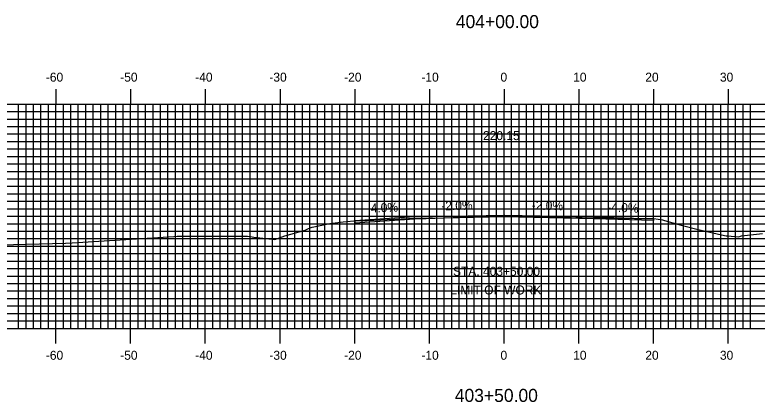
# Model space of a CAD drawing. Extents: x 850955 to 851298, y 364785 to 365005.
# Drawn here: x 851055.2 to 851154.6, y 364893.4 to 364945.2 of the extents above; entities that cross this region are included whole.
import ezdxf

# ---------------------------------------------------------------- set-up
doc = ezdxf.new("R2010")
doc.units = 0
for name, color, linetype in [('ANNOTATION', 7, 'Continuous'), ('D_Roadway_Centerline', 7, 'Continuous'), ('D_Roadway_Centerline_Text', 7, 'Continuous'), ('D_Roadway_Edge_Shoulder', 7, 'Continuous'), ('D_Roadway_Edge_TW', 7, 'Continuous'), ('D_Text_Standard', 7, 'Continuous'), ('H_V ANNOTATION', 7, 'Continuous'), ('MAJOR', 7, 'Continuous'), ('MINOR', 7, 'Continuous'), ('S_Roadway_Centerline', 7, 'Continuous')]:
    doc.layers.add(name, color=color, linetype=linetype)

msp = doc.modelspace()

# ---------------------------------------------------------------- linework, layer by layer
at = {"layer": 'D_Roadway_Edge_Shoulder'}
for points in [[(851108.678, 364918.143), (851100.678, 364917.609), (851100.678, 364917.359), (851108.678, 364917.893)], [(851132.678, 364918.143), (851140.678, 364917.904), (851140.678, 364917.654), (851132.678, 364917.893)]]:
    msp.add_lwpolyline(points, close=True, dxfattribs=at)
at = {"layer": 'D_Roadway_Edge_TW'}
msp.add_lwpolyline([(851108.678, 364917.893), (851108.678, 364918.143), (851120.678, 364918.383), (851132.678, 364918.143), (851132.678, 364917.893), (851120.678, 364918.133)], close=True, dxfattribs=at)
at = {"layer": 'MAJOR'}
for p, q in [((851060.678, 364935.237), (851060.678, 364933.233)), ((851070.678, 364935.237), (851070.678, 364933.233)), ((851080.678, 364935.237), (851080.678, 364933.233)), ((851090.678, 364935.237), (851090.678, 364933.233)), ((851100.678, 364935.237), (851100.678, 364933.233)), ((851110.678, 364935.237), (851110.678, 364933.233)), ((851120.678, 364935.237), (851120.678, 364933.233)), ((851130.678, 364935.237), (851130.678, 364933.233)), ((851140.678, 364935.237), (851140.678, 364933.233)), ((851150.678, 364935.237), (851150.678, 364933.233)), ((850980.678, 364933.233), (851260.678, 364933.233)), ((850980.678, 364933.233), (851260.678, 364933.233)), ((851060.678, 364903.233), (851060.678, 364933.233)), ((851070.678, 364903.233), (851070.678, 364933.233)), ((851080.678, 364903.233), (851080.678, 364933.233)), ((851090.678, 364903.233), (851090.678, 364933.233)), ((851100.678, 364903.233), (851100.678, 364933.233)), ((851110.678, 364903.233), (851110.678, 364933.233)), ((851120.678, 364903.233), (851120.678, 364933.233)), ((851130.678, 364903.233), (851130.678, 364933.233)), ((851140.678, 364903.233), (851140.678, 364933.233)), ((851150.678, 364903.233), (851150.678, 364933.233)), ((850980.678, 364928.233), (851260.678, 364928.233)), ((850980.678, 364923.233), (851260.678, 364923.233)), ((850980.678, 364918.233), (851260.678, 364918.233)), ((850980.678, 364913.233), (851260.678, 364913.233)), ((850980.678, 364908.233), (851260.678, 364908.233)), ((850980.678, 364903.233), (851260.678, 364903.233)), ((850980.678, 364903.233), (851260.678, 364903.233)), ((851060.678, 364901.229), (851060.678, 364903.233)), ((851070.678, 364901.229), (851070.678, 364903.233)), ((851080.678, 364901.229), (851080.678, 364903.233)), ((851090.678, 364901.229), (851090.678, 364903.233)), ((851100.678, 364901.229), (851100.678, 364903.233)), ((851110.678, 364901.229), (851110.678, 364903.233)), ((851120.678, 364901.229), (851120.678, 364903.233)), ((851130.678, 364901.229), (851130.678, 364903.233)), ((851140.678, 364901.229), (851140.678, 364903.233)), ((851150.678, 364901.229), (851150.678, 364903.233))]:
    msp.add_line(p, q, dxfattribs=at)
at = {"layer": 'MINOR'}
for p, q in [((851055.678, 364903.233), (851055.678, 364933.233)), ((851056.678, 364903.233), (851056.678, 364933.233)), ((851057.678, 364903.233), (851057.678, 364933.233)), ((851058.678, 364903.233), (851058.678, 364933.233)), ((851059.678, 364903.233), (851059.678, 364933.233)), ((851061.678, 364903.233), (851061.678, 364933.233)), ((851062.678, 364903.233), (851062.678, 364933.233)), ((851063.678, 364903.233), (851063.678, 364933.233)), ((851064.678, 364903.233), (851064.678, 364933.233)), ((851065.678, 364903.233), (851065.678, 364933.233)), ((851066.678, 364903.233), (851066.678, 364933.233)), ((851067.678, 364903.233), (851067.678, 364933.233)), ((851068.678, 364903.233), (851068.678, 364933.233)), ((851069.678, 364903.233), (851069.678, 364933.233)), ((851071.678, 364903.233), (851071.678, 364933.233)), ((851072.678, 364903.233), (851072.678, 364933.233)), ((851073.678, 364903.233), (851073.678, 364933.233)), ((851074.678, 364903.233), (851074.678, 364933.233)), ((851075.678, 364903.233), (851075.678, 364933.233)), ((851076.678, 364903.233), (851076.678, 364933.233)), ((851077.678, 364903.233), (851077.678, 364933.233)), ((851078.678, 364903.233), (851078.678, 364933.233)), ((851079.678, 364903.233), (851079.678, 364933.233)), ((851081.678, 364903.233), (851081.678, 364933.233)), ((851082.678, 364903.233), (851082.678, 364933.233)), ((851083.678, 364903.233), (851083.678, 364933.233)), ((851084.678, 364903.233), (851084.678, 364933.233)), ((851085.678, 364903.233), (851085.678, 364933.233)), ((851086.678, 364903.233), (851086.678, 364933.233)), ((851087.678, 364903.233), (851087.678, 364933.233)), ((851088.678, 364903.233), (851088.678, 364933.233)), ((851089.678, 364903.233), (851089.678, 364933.233)), ((851091.678, 364903.233), (851091.678, 364933.233)), ((851092.678, 364903.233), (851092.678, 364933.233)), ((851093.678, 364903.233), (851093.678, 364933.233)), ((851094.678, 364903.233), (851094.678, 364933.233)), ((851095.678, 364903.233), (851095.678, 364933.233)), ((851096.678, 364903.233), (851096.678, 364933.233)), ((851097.678, 364903.233), (851097.678, 364933.233)), ((851098.678, 364903.233), (851098.678, 364933.233)), ((851099.678, 364903.233), (851099.678, 364933.233)), ((851101.678, 364903.233), (851101.678, 364933.233)), ((851102.678, 364903.233), (851102.678, 364933.233)), ((851103.678, 364903.233), (851103.678, 364933.233)), ((851104.678, 364903.233), (851104.678, 364933.233)), ((851105.678, 364903.233), (851105.678, 364933.233)), ((851106.678, 364903.233), (851106.678, 364933.233)), ((851107.678, 364903.233), (851107.678, 364933.233)), ((851108.678, 364903.233), (851108.678, 364933.233)), ((851109.678, 364903.233), (851109.678, 364933.233)), ((851111.678, 364903.233), (851111.678, 364933.233)), ((851112.678, 364903.233), (851112.678, 364933.233)), ((851113.678, 364903.233), (851113.678, 364933.233)), ((851114.678, 364903.233), (851114.678, 364933.233)), ((851115.678, 364903.233), (851115.678, 364933.233)), ((851116.678, 364903.233), (851116.678, 364933.233)), ((851117.678, 364903.233), (851117.678, 364933.233)), ((851118.678, 364903.233), (851118.678, 364933.233)), ((851119.678, 364903.233), (851119.678, 364933.233)), ((851121.678, 364903.233), (851121.678, 364933.233)), ((851122.678, 364903.233), (851122.678, 364933.233)), ((851123.678, 364903.233), (851123.678, 364933.233)), ((851124.678, 364903.233), (851124.678, 364933.233)), ((851125.678, 364903.233), (851125.678, 364933.233)), ((851126.678, 364903.233), (851126.678, 364933.233)), ((851127.678, 364903.233), (851127.678, 364933.233)), ((851128.678, 364903.233), (851128.678, 364933.233)), ((851129.678, 364903.233), (851129.678, 364933.233)), ((851131.678, 364903.233), (851131.678, 364933.233)), ((851132.678, 364903.233), (851132.678, 364933.233)), ((851133.678, 364903.233), (851133.678, 364933.233)), ((851134.678, 364903.233), (851134.678, 364933.233)), ((851135.678, 364903.233), (851135.678, 364933.233)), ((851136.678, 364903.233), (851136.678, 364933.233)), ((851137.678, 364903.233), (851137.678, 364933.233)), ((851138.678, 364903.233), (851138.678, 364933.233)), ((851139.678, 364903.233), (851139.678, 364933.233)), ((851141.678, 364903.233), (851141.678, 364933.233)), ((851142.678, 364903.233), (851142.678, 364933.233)), ((851143.678, 364903.233), (851143.678, 364933.233)), ((851144.678, 364903.233), (851144.678, 364933.233)), ((851145.678, 364903.233), (851145.678, 364933.233)), ((851146.678, 364903.233), (851146.678, 364933.233)), ((851147.678, 364903.233), (851147.678, 364933.233)), ((851148.678, 364903.233), (851148.678, 364933.233)), ((851149.678, 364903.233), (851149.678, 364933.233)), ((851151.678, 364903.233), (851151.678, 364933.233)), ((851152.678, 364903.233), (851152.678, 364933.233)), ((851153.678, 364903.233), (851153.678, 364933.233)), ((850980.678, 364932.233), (851260.678, 364932.233)), ((850980.678, 364931.233), (851260.678, 364931.233)), ((850980.678, 364930.233), (851260.678, 364930.233)), ((850980.678, 364929.233), (851260.678, 364929.233)), ((850980.678, 364927.233), (851260.678, 364927.233)), ((850980.678, 364926.233), (851260.678, 364926.233)), ((850980.678, 364925.233), (851260.678, 364925.233)), ((850980.678, 364924.233), (851260.678, 364924.233)), ((850980.678, 364922.233), (851260.678, 364922.233)), ((850980.678, 364921.233), (851260.678, 364921.233)), ((850980.678, 364920.233), (851260.678, 364920.233)), ((850980.678, 364919.233), (851260.678, 364919.233)), ((850980.678, 364917.233), (851260.678, 364917.233)), ((850980.678, 364916.233), (851260.678, 364916.233)), ((850980.678, 364915.233), (851260.678, 364915.233)), ((850980.678, 364914.233), (851260.678, 364914.233)), ((850980.678, 364912.233), (851260.678, 364912.233)), ((850980.678, 364911.233), (851260.678, 364911.233)), ((850980.678, 364910.233), (851260.678, 364910.233)), ((850980.678, 364909.233), (851260.678, 364909.233)), ((850980.678, 364907.233), (851260.678, 364907.233)), ((850980.678, 364906.233), (851260.678, 364906.233)), ((850980.678, 364905.233), (851260.678, 364905.233)), ((850980.678, 364904.233), (851260.678, 364904.233))]:
    msp.add_line(p, q, dxfattribs=at)
at = {"layer": 'S_Roadway_Centerline'}
msp.add_lwpolyline([(851044.483, 364914.182), (851061.947, 364914.635), (851062.845, 364914.668), (851076.465, 364915.51), (851076.91, 364915.544), (851078.228, 364915.581), (851078.704, 364915.554), (851081.549, 364915.547), (851086.307, 364915.554), (851086.747, 364915.524), (851087.162, 364915.429), (851090.002, 364915.105), (851091.329, 364915.593), (851094.03, 364916.358), (851094.499, 364916.591), (851094.979, 364916.749), (851097.354, 364917.276), (851099.143, 364917.462), (851101.067, 364917.643), (851102.327, 364917.671), (851105.927, 364917.821), (851107.879, 364917.912), (851110.232, 364917.941), (851112.586, 364918.01), (851119.112, 364918.248), (851120.786, 364918.393), (851123.741, 364918.222), (851131.146, 364918.001), (851132.702, 364917.971), (851133.367, 364918.016), (851138.13, 364917.94), (851140.714, 364917.909), (851141.871, 364917.734), (851142.141, 364917.672), (851144.383, 364917.053), (851146.667, 364916.442), (851150.179, 364915.654), (851150.423, 364915.601), (851150.542, 364915.592), (851152.117, 364915.489), (851152.313, 364915.575), (851152.465, 364915.629), (851155.288, 364915.899)], dxfattribs=at)

# ---------------------------------------------------------------- texts
at = {"layer": 'ANNOTATION'}
for s, rotation, p in [('-2.0%', 1.14576, (851112.284, 364919.016)), ('-2.0%', 358.85424, (851124.364, 364919.11)), ('-4.0%', 2.29061, (851102.31, 364918.69)), ('-4.0%', 357.70939, (851134.47, 364918.873))]:
    msp.add_text(s, height=1.2, rotation=rotation, dxfattribs=at).set_placement(p)
at = {"layer": 'D_Roadway_Centerline'}
for s, p in [('C', (851120.673, 364918.383)), ('L', (851120.678, 364918.376))]:
    msp.add_text(s, height=0.0146, dxfattribs=at).set_placement(p)
at = {"layer": 'D_Roadway_Centerline_Text'}
msp.add_text('220.15', height=1.2, dxfattribs=at).set_placement((851117.858, 364928.413))
at = {"layer": 'D_Text_Standard'}
for s, p in [('STA. 403+50.00', (851113.846, 364910.264)), ('LIMIT OF WORK', (851113.472, 364907.764))]:
    msp.add_text(s, height=1.2, dxfattribs=at).set_placement(p)
at = {"layer": 'H_V ANNOTATION'}
for s, height, p in [('404+00.00', 1.75, (851114.217, 364943.389)), ('-60', 1.2, (851059.33, 364936.233)), ('-50', 1.2, (851069.287, 364936.233)), ('-40', 1.2, (851079.33, 364936.233)), ('-30', 1.2, (851089.255, 364936.233)), ('-20', 1.2, (851099.265, 364936.233)), ('-10', 1.2, (851109.608, 364936.233)), ('0', 1.2, (851120.196, 364936.233)), ('10', 1.2, (851129.929, 364936.233)), ('20', 1.2, (851139.586, 364936.233)), ('30', 1.2, (851149.576, 364936.233)), ('-60', 1.2, (851059.33, 364899.033)), ('-50', 1.2, (851069.287, 364899.033)), ('-40', 1.2, (851079.33, 364899.033)), ('-30', 1.2, (851089.255, 364899.033)), ('-20', 1.2, (851099.265, 364899.033)), ('-10', 1.2, (851109.608, 364899.033)), ('0', 1.2, (851120.196, 364899.033)), ('10', 1.2, (851129.929, 364899.033)), ('20', 1.2, (851139.586, 364899.033)), ('30', 1.2, (851149.576, 364899.033)), ('403+50.00', 1.75, (851114.077, 364893.389))]:
    msp.add_text(s, height=height, dxfattribs=at).set_placement(p)
at = {"layer": 'S_Roadway_Centerline'}
for s, p in [('L', (851120.777, 364918.385)), ('C', (851120.78, 364918.393))]:
    msp.add_text(s, height=0.0146, dxfattribs=at).set_placement(p)

doc.saveas('drawing.dxf')
